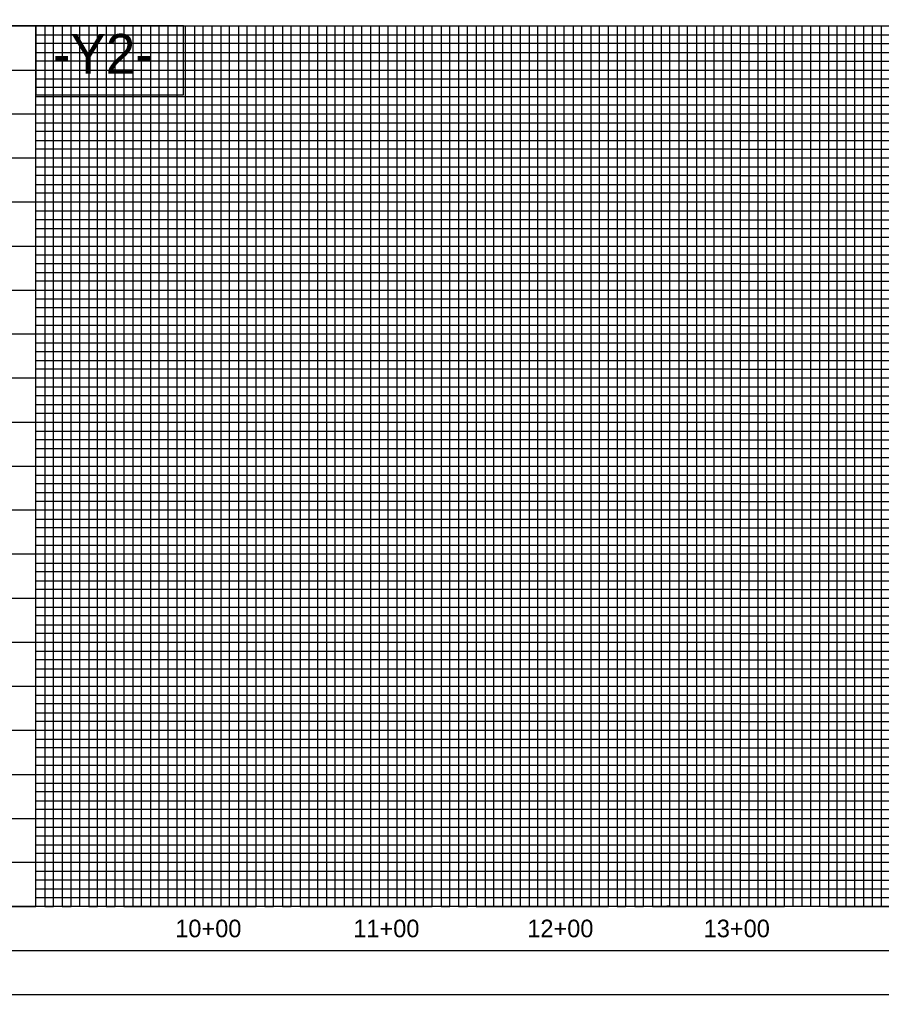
# Model space of a CAD drawing. Extents: x 1524869 to 1526553, y 501099 to 502199.
# Drawn here: x 1525527 to 1526016, y 501099 to 501652 of the extents above; entities that cross this region are included whole.
import ezdxf

# ---------------------------------------------------------------- set-up
doc = ezdxf.new("R2010")
doc.units = 0
for name, color, linetype in [('Exist Vertical Profile Horizontal Axis Label Major', 7, 'Continuous'), ('Prop Grid Mask', 7, 'Continuous'), ('Prop Horizontal Alignment Curve and Spiral Data', 7, 'Continuous'), ('Sheet Layout Profile Border Port 1', 7, 'Continuous'), ('Sheet Plot Border Outside CELL', 7, 'Continuous'), ('Sheet Profile CELL', 7, 'Continuous'), ('Sheet Profile Grid Major CELL', 7, 'Continuous'), ('Sheet Profile Grid Middle CELL', 7, 'Continuous'), ('Sheet Profile Grid Minor CELL', 7, 'Continuous')]:
    doc.layers.add(name, color=color, linetype=linetype)

msp = doc.modelspace()

# ---------------------------------------------------------------- linework, layer by layer
at = {"layer": 'Prop Grid Mask'}
msp.add_lwpolyline([(1525536.08, 501609.52), (1525619.97, 501609.52), (1525619.97, 501648.56), (1525536.08, 501648.56)], close=True, dxfattribs=at)
at = {"layer": 'Sheet Layout Profile Border Port 1'}
msp.add_lwpolyline([(1525536.08, 501648.56), (1526486.08, 501648.56), (1526486.08, 501148.56), (1525536.08, 501148.56)], close=True, dxfattribs=at)
at = {"layer": 'Sheet Plot Border Outside CELL'}
msp.add_lwpolyline([(1524869.08, 501098.56), (1526553.08, 501098.56), (1526553.08, 502198.56), (1524869.08, 502198.56)], close=True, dxfattribs=at)
at = {"layer": 'Sheet Profile CELL'}
for p, q in [((1525036.08, 501648.56), (1526536.08, 501648.56)), ((1526536.08, 501148.56), (1525036.08, 501148.56)), ((1525036.08, 501123.56), (1526536.08, 501123.56))]:
    msp.add_line(p, q, dxfattribs=at)
for points in [[(1526536.08, 502173.56), (1525036.08, 502173.56), (1525036.08, 501123.56), (1526536.08, 501123.56)], [(1525486.08, 501148.56), (1525536.08, 501148.56), (1525536.08, 501648.56), (1525486.08, 501648.56)]]:
    msp.add_lwpolyline(points, close=True, dxfattribs=at)
at = {"layer": 'Sheet Profile Grid Major CELL'}
for p, q in [((1525536.08, 501648.56), (1525586.08, 501648.56)), ((1525636.08, 501648.56), (1525686.08, 501648.56)), ((1525736.08, 501648.56), (1525786.08, 501648.56)), ((1525836.08, 501648.56), (1525886.08, 501648.56)), ((1525936.08, 501648.56), (1525986.08, 501648.56))]:
    msp.add_line(p, q, dxfattribs=at)
for points in [[(1525486.08, 501148.56), (1525536.08, 501148.56), (1525536.08, 501648.56), (1525586.08, 501648.56), (1525586.08, 501148.56), (1525636.08, 501148.56), (1525636.08, 501648.56), (1525686.08, 501648.56), (1525686.08, 501148.56), (1525736.08, 501148.56), (1525736.08, 501648.56), (1525786.08, 501648.56), (1525786.08, 501148.56), (1525836.08, 501148.56), (1525836.08, 501648.56), (1525886.08, 501648.56), (1525886.08, 501148.56), (1525936.08, 501148.56), (1525936.08, 501648.56), (1525986.08, 501648.56), (1525986.08, 501148.56), (1526036.08, 501148.56)], [(1526536.08, 501598.56), (1525036.08, 501598.56)], [(1526536.08, 501548.56), (1525036.08, 501548.56), (1525036.08, 501498.56), (1526536.08, 501498.56)], [(1526536.08, 501448.56), (1525036.08, 501448.56), (1525036.08, 501398.56), (1526536.08, 501398.56)], [(1526536.08, 501348.56), (1525036.08, 501348.56), (1525036.08, 501298.56), (1526536.08, 501298.56)], [(1526536.08, 501248.56), (1525036.08, 501248.56), (1525036.08, 501248.56), (1525036.08, 501198.56), (1526536.08, 501198.56)], [(1526536.08, 501148.56), (1525036.08, 501148.56)]]:
    msp.add_lwpolyline(points, dxfattribs=at)
at = {"layer": 'Sheet Profile Grid Middle CELL'}
for p, q in [((1525961.08, 501148.56), (1525961.08, 501648.56)), ((1526011.08, 501148.56), (1526011.08, 501648.56))]:
    msp.add_line(p, q, dxfattribs=at)
for points in [[(1525561.08, 501148.56), (1525561.08, 501648.56), (1525611.08, 501648.56), (1525611.08, 501148.56), (1525661.08, 501148.56), (1525661.08, 501148.56), (1525661.08, 501648.56), (1525711.08, 501648.56), (1525711.08, 501148.56), (1525761.08, 501148.56), (1525761.08, 501648.56), (1525811.08, 501648.56), (1525811.08, 501148.56), (1525861.08, 501148.56), (1525861.08, 501648.56), (1525911.08, 501648.56), (1525911.08, 501148.56), (1525961.08, 501148.56)], [(1525961.08, 501648.56), (1526011.08, 501648.56)], [(1526011.08, 501148.56), (1526061.08, 501148.56), (1526061.08, 501648.56), (1526111.08, 501648.56), (1526111.08, 501148.56), (1526161.08, 501148.56), (1526161.08, 501648.56), (1526211.08, 501648.56), (1526211.08, 501148.56), (1526261.08, 501148.56), (1526261.08, 501648.56), (1526311.08, 501648.56), (1526311.08, 501148.56), (1526361.08, 501148.56), (1526361.08, 501648.56), (1526411.08, 501648.56), (1526411.08, 501148.56), (1526461.08, 501148.56), (1526461.08, 501648.56)], [(1525036.08, 501623.56), (1526536.08, 501623.56)], [(1526536.08, 501573.56), (1525036.08, 501573.56), (1525036.08, 501523.56), (1526536.08, 501523.56)], [(1526536.08, 501473.56), (1525036.08, 501473.56), (1525036.08, 501423.56), (1526536.08, 501423.56)], [(1526536.08, 501373.56), (1525036.08, 501373.56), (1525036.08, 501323.56), (1526536.08, 501323.56)], [(1526536.08, 501273.56), (1525036.08, 501273.56), (1525036.08, 501223.56), (1526536.08, 501223.56)], [(1526536.08, 501173.56), (1525036.08, 501173.56)]]:
    msp.add_lwpolyline(points, dxfattribs=at)
at = {"layer": 'Sheet Profile Grid Minor CELL'}
for p, q in [((1525941.08, 501148.56), (1525941.08, 501648.56)), ((1525946.08, 501148.56), (1525946.08, 501648.56)), ((1525951.08, 501148.56), (1525951.08, 501648.56)), ((1525956.08, 501148.56), (1525956.08, 501648.56)), ((1525966.08, 501148.56), (1525966.08, 501648.56)), ((1525971.08, 501148.56), (1525971.08, 501648.56)), ((1525976.08, 501148.56), (1525976.08, 501648.56)), ((1525981.08, 501148.56), (1525981.08, 501648.56)), ((1525991.08, 501148.56), (1525991.08, 501648.56)), ((1525996.08, 501148.56), (1525996.08, 501648.56)), ((1526001.08, 501148.56), (1526001.08, 501648.56)), ((1526006.08, 501148.56), (1526006.08, 501648.56)), ((1526016.08, 501148.56), (1526016.08, 501648.56)), ((1525536.08, 501643.56), (1525936.08, 501643.56)), ((1525936.08, 501643.56), (1526036.08, 501643.56)), ((1525936.08, 501638.56), (1525536.08, 501638.56)), ((1525536.08, 501633.56), (1525936.08, 501633.56)), ((1525936.08, 501638.56), (1526036.08, 501638.56)), ((1525936.08, 501633.56), (1526036.08, 501633.56)), ((1525936.08, 501628.56), (1525536.08, 501628.56)), ((1525936.08, 501628.56), (1526036.08, 501628.56)), ((1525536.08, 501618.56), (1525936.08, 501618.56)), ((1525936.08, 501618.56), (1526036.08, 501618.56)), ((1525936.08, 501613.56), (1525536.08, 501613.56)), ((1525936.08, 501613.56), (1526036.08, 501613.56)), ((1525536.08, 501608.56), (1525936.08, 501608.56)), ((1525936.08, 501608.56), (1526036.08, 501608.56)), ((1525936.08, 501603.56), (1525536.08, 501603.56)), ((1525936.08, 501603.56), (1526036.08, 501603.56)), ((1525536.08, 501593.56), (1525936.08, 501593.56)), ((1525936.08, 501593.56), (1526036.08, 501593.56)), ((1525936.08, 501588.56), (1525536.08, 501588.56)), ((1525536.08, 501583.56), (1525936.08, 501583.56)), ((1525936.08, 501588.56), (1526036.08, 501588.56)), ((1525936.08, 501583.56), (1526036.08, 501583.56)), ((1525936.08, 501578.56), (1525536.08, 501578.56)), ((1525936.08, 501578.56), (1526036.08, 501578.56)), ((1525536.08, 501568.56), (1525936.08, 501568.56)), ((1525936.08, 501568.56), (1526036.08, 501568.56)), ((1525936.08, 501563.56), (1525536.08, 501563.56)), ((1525936.08, 501563.56), (1526036.08, 501563.56)), ((1525536.08, 501558.56), (1525936.08, 501558.56)), ((1525936.08, 501558.56), (1526036.08, 501558.56)), ((1525936.08, 501553.56), (1525536.08, 501553.56)), ((1525936.08, 501553.56), (1526036.08, 501553.56)), ((1525536.08, 501543.56), (1525936.08, 501543.56)), ((1525936.08, 501543.56), (1526036.08, 501543.56)), ((1525936.08, 501538.56), (1525536.08, 501538.56)), ((1525536.08, 501533.56), (1525936.08, 501533.56)), ((1525936.08, 501538.56), (1526036.08, 501538.56)), ((1525936.08, 501533.56), (1526036.08, 501533.56)), ((1525936.08, 501528.56), (1525536.08, 501528.56)), ((1525936.08, 501528.56), (1526036.08, 501528.56)), ((1525536.08, 501518.56), (1525936.08, 501518.56)), ((1525936.08, 501518.56), (1526036.08, 501518.56)), ((1525936.08, 501513.56), (1525536.08, 501513.56)), ((1525936.08, 501513.56), (1526036.08, 501513.56)), ((1525536.08, 501508.56), (1525936.08, 501508.56)), ((1525936.08, 501508.56), (1526036.08, 501508.56)), ((1525936.08, 501503.56), (1525536.08, 501503.56)), ((1525936.08, 501503.56), (1526036.08, 501503.56)), ((1525536.08, 501493.56), (1525936.08, 501493.56)), ((1525936.08, 501493.56), (1526036.08, 501493.56)), ((1525936.08, 501488.56), (1525536.08, 501488.56)), ((1525936.08, 501488.56), (1526036.08, 501488.56)), ((1525536.08, 501483.56), (1525936.08, 501483.56)), ((1525936.08, 501478.56), (1525536.08, 501478.56)), ((1525936.08, 501483.56), (1526036.08, 501483.56)), ((1525936.08, 501478.56), (1526036.08, 501478.56)), ((1525536.08, 501468.56), (1525936.08, 501468.56)), ((1525936.08, 501468.62), (1526036.08, 501468.62)), ((1525936.08, 501463.56), (1525536.08, 501463.56)), ((1525936.08, 501463.62), (1526036.08, 501463.62)), ((1525536.08, 501458.56), (1525936.08, 501458.56)), ((1525936.08, 501458.62), (1526036.08, 501458.62)), ((1525936.08, 501453.62), (1525536.08, 501453.66)), ((1525936.08, 501453.62), (1526036.08, 501453.62)), ((1525536.08, 501443.56), (1525936.08, 501443.56)), ((1525936.08, 501443.56), (1526036.08, 501443.56)), ((1525936.08, 501438.56), (1525536.08, 501438.56)), ((1525936.08, 501438.56), (1526036.08, 501438.56)), ((1525536.08, 501433.56), (1525936.08, 501433.56)), ((1525936.08, 501428.56), (1525536.08, 501428.56)), ((1525936.08, 501433.56), (1526036.08, 501433.56)), ((1525936.08, 501428.56), (1526036.08, 501428.56)), ((1525536.08, 501418.56), (1525936.08, 501418.56)), ((1525936.08, 501418.56), (1526036.08, 501418.56)), ((1525936.08, 501413.56), (1525536.08, 501413.56)), ((1525936.08, 501413.56), (1526036.08, 501413.56)), ((1525536.08, 501408.56), (1525936.08, 501408.56)), ((1525936.08, 501408.56), (1526036.08, 501408.56)), ((1525936.08, 501403.56), (1525536.08, 501403.56)), ((1525936.08, 501403.56), (1526036.08, 501403.56)), ((1525536.08, 501393.56), (1525936.08, 501393.56)), ((1525936.08, 501393.56), (1526036.08, 501393.56)), ((1525936.08, 501388.56), (1525536.08, 501388.56)), ((1525936.08, 501388.56), (1526036.08, 501388.56)), ((1525536.08, 501383.56), (1525936.08, 501383.56)), ((1525936.08, 501378.56), (1525536.08, 501378.56)), ((1525936.08, 501383.56), (1526036.08, 501383.56)), ((1525936.08, 501378.56), (1526036.08, 501378.56)), ((1525536.08, 501368.56), (1525936.08, 501368.56)), ((1525936.08, 501368.56), (1526036.08, 501368.56)), ((1525936.08, 501363.56), (1525536.08, 501363.56)), ((1525936.08, 501363.56), (1526036.08, 501363.56)), ((1525536.08, 501358.56), (1525936.08, 501358.56)), ((1525936.08, 501358.56), (1526036.08, 501358.56)), ((1525936.08, 501353.56), (1525536.08, 501353.56)), ((1525936.08, 501353.56), (1526036.08, 501353.56)), ((1525536.08, 501343.56), (1525936.08, 501343.56)), ((1525936.08, 501343.56), (1526036.08, 501343.56)), ((1525936.08, 501338.56), (1525536.08, 501338.56)), ((1525936.08, 501338.56), (1526036.08, 501338.56)), ((1525536.08, 501333.56), (1525936.08, 501333.56)), ((1525936.08, 501333.56), (1526036.08, 501333.56)), ((1525936.08, 501328.56), (1525536.08, 501328.56)), ((1525936.08, 501328.56), (1526036.08, 501328.56)), ((1525536.08, 501318.56), (1525936.08, 501318.56)), ((1525936.08, 501318.56), (1526036.08, 501318.56)), ((1525936.08, 501313.56), (1525536.08, 501313.56)), ((1525936.08, 501313.56), (1526036.08, 501313.56)), ((1525536.08, 501308.56), (1525936.08, 501308.56)), ((1525936.08, 501308.56), (1526036.08, 501308.56)), ((1525936.08, 501303.56), (1525536.08, 501303.56)), ((1525936.08, 501303.56), (1526036.08, 501303.56)), ((1525536.08, 501293.56), (1525936.08, 501293.56)), ((1525936.08, 501293.56), (1526036.08, 501293.56)), ((1525936.08, 501288.56), (1525536.08, 501288.56)), ((1525936.08, 501288.56), (1526036.08, 501288.56)), ((1525536.08, 501283.56), (1525936.08, 501283.56)), ((1525936.08, 501283.56), (1526036.08, 501283.56)), ((1525936.08, 501278.56), (1525536.08, 501278.56)), ((1525936.08, 501278.56), (1526036.08, 501278.56)), ((1525536.08, 501268.56), (1525936.08, 501268.56)), ((1525936.08, 501268.56), (1526036.08, 501268.56)), ((1525936.08, 501263.56), (1525536.08, 501263.56)), ((1525936.08, 501263.56), (1526036.08, 501263.56)), ((1525536.08, 501258.56), (1525936.08, 501258.56)), ((1525936.08, 501258.56), (1526036.08, 501258.56)), ((1525936.08, 501253.56), (1525536.08, 501253.56)), ((1525936.08, 501253.56), (1526036.08, 501253.56)), ((1525536.08, 501243.56), (1525936.08, 501243.56)), ((1525936.08, 501243.56), (1526036.08, 501243.56)), ((1525936.08, 501238.56), (1525536.08, 501238.56)), ((1525936.08, 501238.56), (1526036.08, 501238.56)), ((1525536.08, 501233.56), (1525936.08, 501233.56)), ((1525936.08, 501233.56), (1526036.08, 501233.56)), ((1525936.08, 501228.56), (1525536.08, 501228.56)), ((1525936.08, 501228.56), (1526036.08, 501228.56)), ((1525536.08, 501218.56), (1525936.08, 501218.56)), ((1525936.08, 501218.56), (1526036.08, 501218.56)), ((1525936.08, 501213.56), (1525536.08, 501213.56)), ((1525936.08, 501213.56), (1526036.08, 501213.56)), ((1525536.08, 501208.56), (1525936.08, 501208.56)), ((1525936.08, 501208.56), (1526036.08, 501208.56)), ((1525936.08, 501203.56), (1525536.08, 501203.56)), ((1525936.08, 501203.56), (1526036.08, 501203.56)), ((1525536.08, 501193.56), (1525936.08, 501193.56)), ((1525936.08, 501193.56), (1526036.08, 501193.56)), ((1525936.08, 501188.56), (1525536.08, 501188.56)), ((1525936.08, 501188.56), (1526036.08, 501188.56)), ((1525536.08, 501183.56), (1525936.08, 501183.56)), ((1525936.08, 501183.56), (1526036.08, 501183.56)), ((1525936.08, 501178.56), (1525536.08, 501178.56)), ((1525936.08, 501178.56), (1526036.08, 501178.56)), ((1525536.08, 501168.56), (1525936.08, 501168.56)), ((1525936.08, 501168.56), (1526036.08, 501168.56)), ((1525936.08, 501163.56), (1525536.08, 501163.56)), ((1525936.08, 501163.56), (1526036.08, 501163.56)), ((1525536.08, 501158.56), (1525936.08, 501158.56)), ((1525936.08, 501158.56), (1526036.08, 501158.56)), ((1525536.08, 501153.56), (1525936.08, 501153.56)), ((1525936.08, 501153.56), (1526036.08, 501153.56))]:
    msp.add_line(p, q, dxfattribs=at)
for points in [[(1525531.08, 501648.56), (1525541.08, 501648.56), (1525541.08, 501148.56), (1525546.08, 501148.56), (1525546.08, 501648.56), (1525551.08, 501648.56), (1525551.08, 501148.56), (1525556.08, 501148.56), (1525556.08, 501648.56), (1525566.08, 501648.56), (1525566.08, 501148.56), (1525571.08, 501148.56), (1525571.08, 501648.56), (1525576.08, 501648.56), (1525576.08, 501148.56), (1525581.08, 501148.56), (1525581.08, 501648.56), (1525591.08, 501648.56), (1525591.08, 501148.56), (1525596.08, 501148.56), (1525596.08, 501648.56), (1525601.08, 501648.56), (1525601.08, 501148.56), (1525606.08, 501148.56), (1525606.08, 501648.56), (1525616.08, 501648.56)], [(1525616.08, 501648.56), (1525616.08, 501148.56), (1525621.08, 501148.56), (1525621.08, 501648.56), (1525626.08, 501648.56), (1525626.08, 501148.56), (1525631.08, 501148.56), (1525631.08, 501648.56), (1525641.08, 501648.56), (1525641.08, 501148.56), (1525646.08, 501148.56), (1525646.08, 501648.56), (1525651.08, 501648.56), (1525651.08, 501148.56), (1525656.08, 501148.56), (1525656.08, 501648.56), (1525666.08, 501648.56), (1525666.08, 501148.56), (1525671.08, 501148.56), (1525671.08, 501648.56), (1525676.08, 501648.56), (1525676.08, 501148.56), (1525681.08, 501148.56), (1525681.08, 501648.56), (1525691.08, 501648.56), (1525691.08, 501148.56), (1525696.08, 501148.56), (1525696.08, 501648.56), (1525701.08, 501648.56), (1525701.08, 501148.56), (1525706.08, 501148.56), (1525706.08, 501648.56), (1525716.08, 501648.56), (1525716.08, 501148.56), (1525721.08, 501148.56), (1525721.08, 501648.56), (1525726.08, 501648.56), (1525726.08, 501148.56), (1525731.08, 501148.56), (1525731.08, 501648.56), (1525741.08, 501648.56), (1525741.08, 501148.56), (1525741.08, 501148.56), (1525746.08, 501148.56), (1525746.08, 501648.56), (1525751.08, 501648.56), (1525751.08, 501148.56), (1525756.08, 501148.56), (1525756.08, 501648.56), (1525766.08, 501648.56), (1525766.08, 501148.56), (1525771.08, 501148.56), (1525771.08, 501648.56), (1525776.08, 501648.56), (1525776.08, 501148.56), (1525781.08, 501148.56), (1525781.08, 501648.56), (1525791.08, 501648.56), (1525791.08, 501148.56), (1525796.08, 501148.56), (1525796.08, 501648.56), (1525801.08, 501648.56), (1525801.08, 501148.56), (1525806.08, 501148.56), (1525806.08, 501648.56), (1525816.08, 501648.56), (1525816.08, 501148.56), (1525821.08, 501148.56), (1525821.08, 501648.56), (1525826.08, 501648.56), (1525826.08, 501148.56), (1525831.08, 501148.56), (1525831.08, 501648.56), (1525841.08, 501648.56), (1525841.08, 501148.56), (1525846.08, 501148.56), (1525846.08, 501648.56), (1525851.08, 501648.56), (1525851.08, 501148.56), (1525856.08, 501148.56), (1525856.08, 501648.56), (1525866.08, 501648.56), (1525866.08, 501148.56), (1525871.08, 501148.56), (1525871.08, 501648.56), (1525876.08, 501648.56), (1525876.08, 501148.56), (1525881.08, 501148.56), (1525881.08, 501648.56), (1525891.08, 501648.56), (1525891.08, 501148.56), (1525895.78, 501149.11), (1525896.08, 501148.56), (1525896.08, 501648.56), (1525901.08, 501648.56), (1525901.08, 501148.56), (1525906.08, 501148.56), (1525906.08, 501648.56), (1525916.08, 501648.56), (1525916.08, 501148.56), (1525921.08, 501148.56)], [(1525921.08, 501148.56), (1525921.08, 501648.56), (1525926.08, 501648.56), (1525926.08, 501148.56), (1525931.08, 501148.56), (1525931.08, 501648.56), (1525941.08, 501648.56)]]:
    msp.add_lwpolyline(points, dxfattribs=at)

# ---------------------------------------------------------------- texts
at = {"layer": 'Exist Vertical Profile Horizontal Axis Label Major'}
for s, p in [('10+00', (1525615.21, 501131.06)), ('11+00', (1525716.27, 501131.06)), ('12+00', (1525815.05, 501131.06)), ('13+00', (1525915.21, 501131.06))]:
    msp.add_text(s, height=10, dxfattribs=at).set_placement(p)
at = {"layer": 'Prop Horizontal Alignment Curve and Spiral Data'}
msp.add_text('-Y2-', height=22.5, rotation=360, dxfattribs=at).set_placement((1525545.71, 501621.53))

doc.saveas('drawing.dxf')
